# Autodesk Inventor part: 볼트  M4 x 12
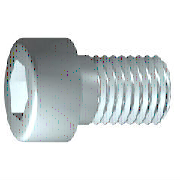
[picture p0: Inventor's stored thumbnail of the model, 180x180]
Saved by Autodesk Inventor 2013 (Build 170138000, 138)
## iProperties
IsCustomPart: 0
Created: 2015-12
Part Number: 볼트  M4 x 12
Material: 스테인리스강
Description: 6각머리 태핑 나사
Document SubType Name: Modeling
Standard: KS B 1003
Designer: mdu
Standards Organization: KS
Language: ko-KR
Size Designation: M 4 x 12
Categories: <MemberInstance><Categories><Category DisplayName="조임쇠" InternalName="e4da775c-781d-43d5-af7c-5136215cf5a6" Mnemonic="FSTN"><Category DisplayName="볼트" InternalN
Density: 8.08 g/cm^3
Mass: 2.29719 g
Surface Area: 3.30853 cm^2
Volume: 0.284306 cm^3
Author: mdu
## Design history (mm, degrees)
sketch "스케치1"
  geometry: L1 (-1, 0)-(12, 0); L2 (12, 0)-(12, 2); L3 (12, 2)-(1.75, 2); L4 (1.75, 2)-(1.32, 2); L5 (1.32, 2)-(0, 2); L6 (0, 2)-(0, 3.5); L7 (0, 3.5)-(-4, 3.5); L8 (-4, 3.5)-(-4, 1.732); L9 (-4, 1.732)-(-2, 1.732); L10 (-2, 1.732)-(-1, 0); L11 (-7.2, 0)-(15.2, 0) reference; L12 (0, -0.7)-(0, 4.2) reference; L13 (1.75, 2)-(0, 2)
  constraints: 22 end point, 6 parallel, 2 collinear, 2 perpendicular, 1 horizontal, 1 point on line
  dimensions: "d1" = 10.25 distance from line of L3.end L2 (= GEL); "d2" = 0.42952 distance of L4.end L3.end (computed from GAL); "d3" = 4 distance between parallel lines of L8 L6 (= KOH); "d4" = 2 distance of L8.end L9.end (= INTI); "d5" = 60 deg angle of L10 L1; "d6" = 4 diameter of L3 L1 (= GD); "d7" = 4 diameter of L5 L1 (= BDM); "d8" = 3.4641 diameter of L9 L1 (= 1.1547 x SW); "d9" = 7 diameter of L7 L1 (= KOD); "d26" = 12 distance between parallel lines of L12 L2 (= NLG)
revolve "본체" sketch "스케치1" stored, may be unused: angle "d10" = 90 deg
sketch "스케치2"
  geometry: L1 (0, -4.9)-(0, 4.9) reference; L2 (-4.9, 0)-(4.9, 0) reference; L3 (1.732, 0)-(0.866, -1.5); L4 (0.866, -1.5)-(-0.866, -1.5); L5 (-0.866, -1.5)-(-1.732, 0); L6 (-1.732, 0)-(-0.866, 1.5); L7 (-0.866, 1.5)-(0.866, 1.5); L8 (0.866, 1.5)-(1.732, 0); 2 further points
  constraints: 12 end point, 1 coincident, 1 horizontal alignment, 1 point on line, 12 other
extrude "슬롯" join sketch "스케치2" stored distance "d11" = 10; taper "d12" = 0 deg
workplane "Work Plane1"
fillet "Fillet2" dims "d30" = 0.1 (= R)
body "Solid1"
fillet "모깎기1" dims "d17" = 0.4 (= RR)
feature "스레드" dims "d13" = 10.25 (= GEL), "d14" = 0
chamfer "모따기1" distance "d15" = 0.42941 (= -0.5 x SPD + 0.5 x GD); stored, may be unused: second distance "d16" = 0.42941 (= GUL), angle "d27" = 45 deg
other parameters: "GD" = 4 (= NND) [user parameter; used in 2 equation terms], "NLG" = 12 [user parameter; used in 1 equation term], "GEL" = 10.25 [user parameter; used in 2 equation terms], "KOD" = 7 [user parameter; used in 1 equation term], "KOH" = 4 [user parameter; used in 1 equation term], "INTI" = 2 [user parameter; used in 1 equation term], "GAL" = 0.42941 (= 0.61345 x PTC) [user parameter; used in 1 equation term], "GUL" = 0.42941 (= 0.61345 x PTC) [user parameter; used in 1 equation term], "BDM" = 4 (= NND) [user parameter; used in 1 equation term], "SW" = 3 [user parameter; used in 2 equation terms], "RR" = 0.4 [user parameter; used in 1 equation term], "SPD" = 3.14117 (= NND - 1.2269 x PTC) [user parameter; used in 1 equation term], "d19" = 0, "d28" = 0, "d29" = 0, "R" = 0.1 [user parameter; used in 1 equation term], "PHH" = 0.2 [user parameter], "GD1" = 3.14117 (= THREADDIA - 1.2269 x PTC) [user parameter], "THREADDIA" = 4 [user parameter; used in 1 equation term], "FAWI" = 45 deg [user parameter], "TPU" = 14.28571 (computed from PTC) [user parameter], "PTC" = 0.7 [user parameter; used in 5 equation terms], "NND" = 4 [user parameter; used in 3 equation terms], "TOA" = 30 deg [user parameter], "E0" = 3.465 (= 1.155 x SW) [user parameter]
